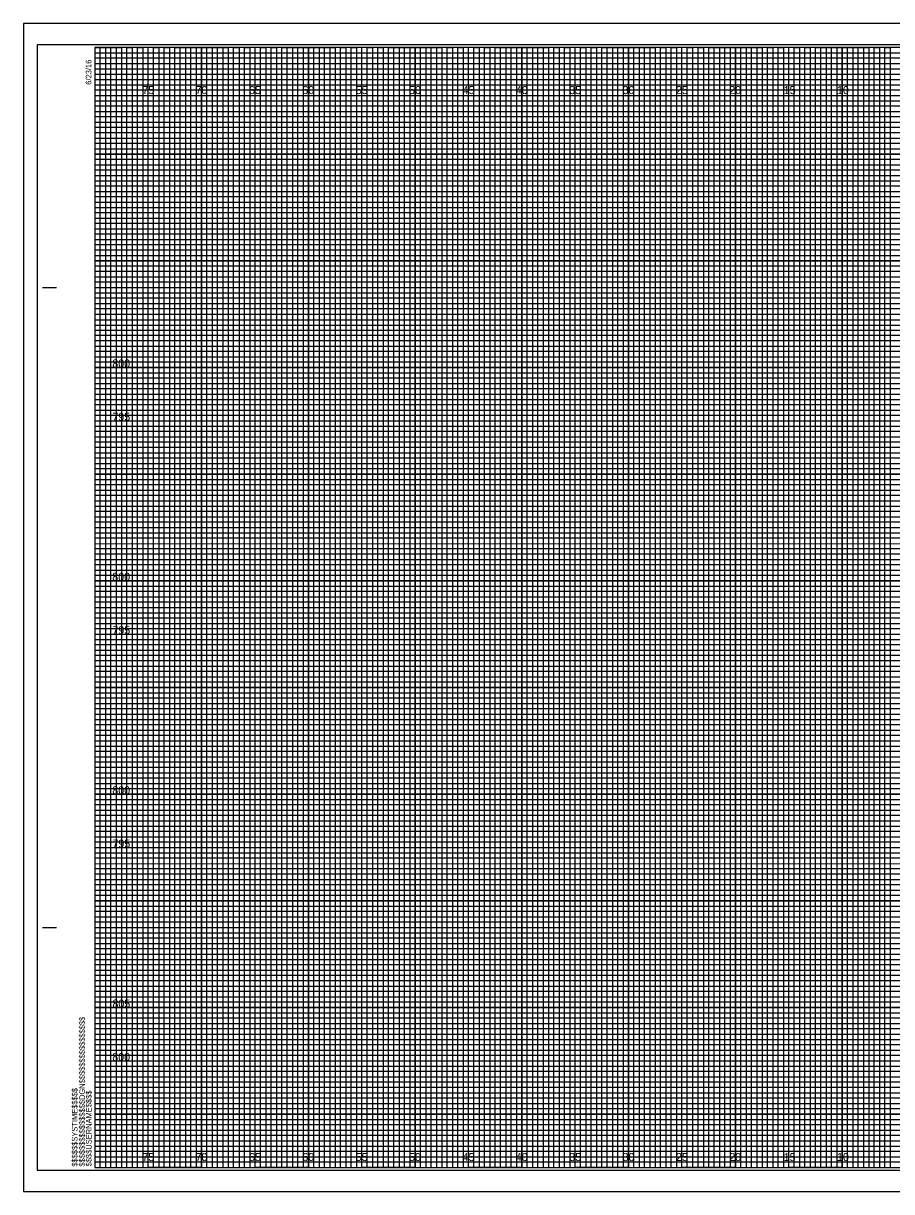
# Model space of a CAD drawing. Extents: x -7 to 162, y -2 to 107.
# Drawn here: x -6.7 to 74.6, y -2.3 to 107.3 of the extents above; entities that cross this region are included whole.
import ezdxf

# ---------------------------------------------------------------- set-up
doc = ezdxf.new("R2010")
doc.units = 0
for name, color, linetype in [('Exist Cross Section Cell', 7, 'Continuous'), ('Exist XS Center Line Elevation Label', 7, 'Continuous'), ('Prop CMT Pvmt Course 2 Wedge', 7, 'Continuous'), ('Prop XS Elevation Labels', 7, 'Continuous'), ('Prop XS Hydro Elevations', 7, 'Continuous'), ('Prop XS SE Text', 7, 'Continuous'), ('Prop XS Side Slope Text', 7, 'Continuous'), ('Sheet Cutting Line CELL', 7, 'Continuous'), ('Sheet DOT Grid CELL', 7, 'Continuous'), ('Sheet Plot Border Inside CELL', 7, 'Continuous'), ('Sheet Plot Border Outside CELL', 7, 'Continuous')]:
    doc.layers.add(name, color=color, linetype=linetype)

msp = doc.modelspace()

# ---------------------------------------------------------------- linework, layer by layer
at = {"layer": 'Exist Cross Section Cell'}
for p, q in [((5, 105), (0, 105)), ((5, 0), (5, 105)), ((15, 105), (10, 105)), ((10, 105), (10, 0)), ((15, 0), (15, 105)), ((25, 105), (20, 105)), ((20, 105), (20, 0)), ((25, 0), (25, 105)), ((35, 105), (30, 105)), ((30, 105), (30, 0)), ((35, 0), (35, 105)), ((45, 105), (40, 105)), ((40, 105), (40, 0)), ((45, 0), (45, 105)), ((55, 105), (50, 105)), ((50, 105), (50, 0)), ((55, 0), (55, 105)), ((65, 105), (60, 105)), ((60, 105), (60, 0)), ((65, 0), (65, 105)), ((75, 105), (70, 105)), ((70, 105), (70, 0)), ((10, 0), (5, 0)), ((20, 0), (15, 0)), ((30, 0), (25, 0)), ((40, 0), (35, 0)), ((50, 0), (45, 0)), ((60, 0), (55, 0)), ((70, 0), (65, 0))]:
    msp.add_line(p, q, dxfattribs=at)
for points in [[(0, 100), (160, 100), (160, 95), (0, 95)], [(0, 90), (160, 90), (160, 85), (0, 85)], [(0, 80), (160, 80), (160, 75), (0, 75)], [(0, 70), (160, 70), (160, 65), (0, 65)], [(0, 60), (160, 60), (160, 55), (0, 55)], [(0, 50), (160, 50), (160, 45), (0, 45)], [(0, 40), (160, 40), (160, 35), (0, 35)], [(0, 30), (160, 30), (160, 25), (0, 25)], [(0, 20), (160, 20), (160, 15), (0, 15)], [(0, 10), (160, 10), (160, 5), (0, 5)]]:
    msp.add_lwpolyline(points, dxfattribs=at)
at = {"layer": 'Exist XS Center Line Elevation Label'}
for points in [[(0, 105), (2.5, 105), (2.5, 0), (7.5, 0), (7.5, 105), (12.5, 105), (12.5, 0), (17.5, 0), (17.5, 105), (22.5, 105), (22.5, 0), (27.5, 0), (27.5, 105), (32.5, 105), (32.5, 0), (37.5, 0), (37.5, 105), (42.5, 105), (42.5, 0), (47.5, 0), (47.5, 105), (52.5, 105), (52.5, 0), (57.5, 0), (57.5, 105), (62.5, 105), (62.5, 0), (67.5, 0), (67.5, 105), (72.5, 105), (72.5, 0), (77.5, 0)], [(0, 102.5), (137.5, 102.5)], [(0, 92.5), (160, 92.5), (160, 97.5), (0, 97.5)], [(0, 82.5), (160, 82.5), (160, 87.5), (0, 87.5)], [(0, 72.5), (160, 72.5), (160, 77.5), (0, 77.5)], [(0, 62.5), (160, 62.5), (160, 67.5), (0, 67.5)], [(0, 52.5), (160, 52.5), (160, 57.5), (0, 57.5)], [(0, 42.5), (160, 42.5), (160, 47.5), (0, 47.5)], [(0, 32.5), (160, 32.5), (160, 37.5), (0, 37.5)], [(0, 22.5), (160, 22.5), (160, 27.5), (0, 27.5)], [(0, 12.5), (160, 12.5), (160, 17.5), (0, 17.5)], [(0, 2.5), (160, 2.5), (160, 7.5), (0, 7.5)]]:
    msp.add_lwpolyline(points, dxfattribs=at)
at = {"layer": 'Prop CMT Pvmt Course 2 Wedge'}
for points in [[(0, 0), (0.5, 0), (0.5, 105), (1, 105), (1, 0)], [(1, 0), (1.5, 0), (1.5, 105), (2, 105), (2, 0)], [(2.5, 0), (3, 0), (3, 105), (3.5, 105), (3.5, 0)], [(3.5, 0), (4, 0), (4, 105), (4.5, 105), (4.5, 0)], [(5, 0), (5.5, 0), (5.5, 105), (6, 105), (6, 0)], [(6, 0), (6.5, 0), (6.5, 105), (7, 105), (7, 0)], [(7.5, 0), (8, 0), (8, 105), (8.5, 105), (8.5, 0)], [(8.5, 0), (9, 0), (9, 105), (9.5, 105), (9.5, 0)], [(10, 0), (10.5, 0), (10.5, 105), (11, 105), (11, 0)], [(11, 0), (11.5, 0), (11.5, 105), (12, 105), (12, 0)], [(12.5, 0), (13, 0), (13, 105), (13.5, 105), (13.5, 0)], [(13.5, 0), (14, 0), (14, 105), (14.5, 105), (14.5, 0)], [(15, 0), (15.5, 0), (15.5, 105), (16, 105), (16, 0)], [(16, 0), (16.5, 0), (16.5, 105), (17, 105), (17, 0)], [(17.5, 0), (18, 0), (18, 105), (18.5, 105), (18.5, 0)], [(18.5, 0), (19, 0), (19, 105), (19.5, 105), (19.5, 0)], [(20, 0), (20.5, 0), (20.5, 105), (21, 105), (21, 0)], [(21, 0), (21.5, 0), (21.5, 105), (22, 105), (22, 0)], [(22.5, 0), (23, 0), (23, 105), (23.5, 105), (23.5, 0)], [(23.5, 0), (24, 0), (24, 105), (24.5, 105), (24.5, 0)], [(25, 0), (25.5, 0), (25.5, 105), (26, 105), (26, 0)], [(26, 0), (26.5, 0), (26.5, 105), (27, 105), (27, 0)], [(27.5, 0), (28, 0), (28, 105), (28.5, 105), (28.5, 0)], [(28.5, 0), (29, 0), (29, 105), (29.5, 105), (29.5, 0)], [(30, 0), (30.5, 0), (30.5, 105), (31, 105), (31, 0)], [(31, 0), (31.5, 0), (31.5, 105), (32, 105), (32, 0)], [(32.5, 0), (33, 0), (33, 105), (33.5, 105), (33.5, 0)], [(33.5, 0), (34, 0), (34, 105), (34.5, 105), (34.5, 0)], [(35, 0), (35.5, 0), (35.5, 105), (36, 105), (36, 0)], [(36, 0), (36.5, 0), (36.5, 105), (37, 105), (37, 0)], [(37.5, 0), (38, 0), (38, 105), (38.5, 105), (38.5, 0)], [(38.5, 0), (39, 0), (39, 105), (39.5, 105), (39.5, 0)], [(40, 0), (40.5, 0), (40.5, 105), (41, 105), (41, 0)], [(41, 0), (41.5, 0), (41.5, 105), (42, 105), (42, 0)], [(42.5, 0), (43, 0), (43, 105), (43.5, 105), (43.5, 0)], [(43.5, 0), (44, 0), (44, 105), (44.5, 105), (44.5, 0)], [(45, 0), (45.5, 0), (45.5, 105), (46, 105), (46, 0)], [(46, 0), (46.5, 0), (46.5, 105), (47, 105), (47, 0)], [(47.5, 0), (48, 0), (48, 105), (48.5, 105), (48.5, 0)], [(48.5, 0), (49, 0), (49, 105), (49.5, 105), (49.5, 0)], [(50, 0), (50.5, 0), (50.5, 105), (51, 105), (51, 0)], [(51, 0), (51.5, 0), (51.5, 105), (52, 105), (52, 0)], [(52.5, 0), (53, 0), (53, 105), (53.5, 105), (53.5, 0)], [(53.5, 0), (54, 0), (54, 105), (54.5, 105), (54.5, 0)], [(55, 0), (55.5, 0), (55.5, 105), (56, 105), (56, 0)], [(56, 0), (56.5, 0), (56.5, 105), (57, 105), (57, 0)], [(57.5, 0), (58, 0), (58, 105), (58.5, 105), (58.5, 0)], [(58.5, 0), (59, 0), (59, 105), (59.5, 105), (59.5, 0)], [(60, 0), (60.5, 0), (60.5, 105), (61, 105), (61, 0)], [(61, 0), (61.5, 0), (61.5, 105), (62, 105), (62, 0)], [(62.5, 0), (63, 0), (63, 105), (63.5, 105), (63.5, 0)], [(63.5, 0), (64, 0), (64, 105), (64.5, 105), (64.5, 0)], [(65, 0), (65.5, 0), (65.5, 105), (66, 105), (66, 0)], [(66, 0), (66.5, 0), (66.5, 105), (67, 105), (67, 0)], [(67.5, 0), (68, 0), (68, 105), (68.5, 105), (68.5, 0)], [(68.5, 0), (69, 0), (69, 105), (69.5, 105), (69.5, 0)], [(70, 0), (70.5, 0), (70.5, 105), (71, 105), (71, 0)], [(71, 0), (71.5, 0), (71.5, 105), (72, 105), (72, 0)], [(72.5, 0), (73, 0), (73, 105), (73.5, 105), (73.5, 0)], [(73.5, 0), (74, 0), (74, 105), (74.5, 105), (74.5, 0)]]:
    msp.add_lwpolyline(points, dxfattribs=at)
at = {"layer": 'Prop XS Hydro Elevations'}
for p, q in [((-4.9, 82.5), (-3.65, 82.5)), ((-4.85, 82.5), (-3.6, 82.5)), ((-4.9, 22.5), (-3.65, 22.5)), ((-4.85, 22.5), (-3.6, 22.5)), ((0, 0), (0, 0)), ((0, 0), (0, 0)), ((0, 0), (0, 0)), ((0, 0), (0, 0)), ((0, 0), (0, 0)), ((0, 0), (0, 0)), ((0, 0), (0, 0))]:
    msp.add_line(p, q, dxfattribs=at)
msp.add_lwpolyline([(160, 105), (0, 105), (0, 0), (160, 0)], close=True, dxfattribs=at)
at = {"layer": 'Prop XS Side Slope Text'}
for p, q in [((0, 104.5), (130, 104.5)), ((130, 103.99), (0, 103.99)), ((0, 103.99), (0, 103.5)), ((0, 103.5), (130, 103.5)), ((130, 102.95), (0, 102.95)), ((0, 102.95), (0, 102)), ((0, 102), (160, 102))]:
    msp.add_line(p, q, dxfattribs=at)
for points in [[(0, 101.5), (135, 101.5), (160, 101.5), (160, 101), (0, 101)], [(0, 100.5), (160, 100.5), (160, 99.5), (0, 99.5)], [(0, 99), (160, 99), (160, 98.5), (0, 98.49)], [(0, 98), (160, 98), (160, 97), (0, 97)], [(0, 96.5), (160, 96.5), (160, 96), (0, 96)], [(0, 95.5), (160, 95.5), (160, 94.5), (0, 94.5)], [(0, 94), (160, 94), (160, 93.5), (0, 93.5)], [(0, 93), (160, 93), (160, 92), (0, 92)], [(0, 91.5), (160, 91.5), (160, 91), (0, 91)], [(0, 90.5), (160, 90.5), (160, 89.5), (0, 89.5)], [(0, 89), (160, 89), (160, 88.5), (0, 88.5)], [(0, 88), (160, 88), (160, 86.98), (160, 86.5), (160, 86), (0, 86)], [(0, 87), (160, 87), (160, 86.5), (0, 86.5)], [(0, 85.5), (160, 85.5), (160, 84.5), (0, 84.52)], [(0, 84.52), (160, 84.5), (160, 84), (0, 84)], [(0, 83.5), (160, 83.5), (160, 83), (0, 83)], [(0, 82), (160, 82), (160, 81.5), (0, 81.5)], [(0, 81), (160, 81), (160, 80.5), (0, 80.5)], [(-0.04, 79.45), (160, 79.45), (160, 78.94), (-0.04, 78.94)], [(0, 78.5), (160, 78.5), (160, 78), (0, 78)], [(0, 77), (160, 77), (160, 76.5), (0, 76.5)], [(0, 76), (160, 76), (160, 75.5), (0, 75.5)], [(0, 74.5), (160, 74.5), (160, 74), (0, 74)], [(0, 73.5), (160, 73.5), (160, 73), (0, 73)], [(0, 72), (160, 72), (160, 71.5), (0, 71.5)], [(0, 71), (160, 71), (160, 70.5), (0, 70.5)], [(0, 69.5), (160, 69.5), (160, 68.99), (0, 69)], [(0, 68.5), (160, 68.5), (160, 68), (0, 68)], [(0, 67), (160, 67), (160, 66.5), (0, 66.5)], [(0, 66), (160, 66), (160, 65.5), (0, 65.5)], [(0, 64.5), (160, 64.5), (160, 64), (0, 64)], [(0, 63.5), (160, 63.5), (160, 63), (0, 63)], [(0, 62), (160, 62), (160, 61.5), (0, 61.5)], [(0, 61), (160, 61), (160, 60.5), (0, 60.5)], [(0, 59.5), (160, 59.5), (160, 59), (0, 59)], [(0, 58.5), (160.03, 58.45), (160, 58), (0, 58)], [(0, 57), (160, 57), (160, 56.5), (0, 56.5)], [(0, 56), (160, 56), (160, 55.5), (0, 55.5)], [(0, 54.5), (160, 54.5), (160, 54), (0, 54)], [(0, 53.5), (160, 53.5), (160, 53), (0, 53)], [(0, 52), (160, 52), (160, 51.5), (0, 51.5)], [(0, 51), (160, 51), (160, 50.5), (0, 50.5)], [(0, 49.5), (160, 49.5), (160, 49), (0, 49)], [(0, 48.5), (160, 48.5), (160, 48), (0, 48)], [(0, 47), (160, 47), (160, 46.5), (0, 46.5)], [(0, 46), (160, 46), (160, 45.5), (0, 45.5)], [(0, 44.5), (160, 44.5), (160, 44), (0, 44)], [(0, 43.5), (160, 43.5), (160, 43), (0, 43)], [(0, 42), (160, 42), (160, 41.5), (0, 41.5)], [(0, 41), (160, 41), (160, 40.5), (0, 40.5)], [(0, 39.5), (160, 39.5), (160, 38.99), (0, 39)], [(0, 38.5), (160, 38.5), (160, 38), (0, 38)], [(0, 37), (160, 37), (160, 36.5), (0, 36.5)], [(0, 36), (160, 36), (160, 35.5), (0, 35.5)], [(0, 34.5), (160, 34.5), (160, 34), (0, 34)], [(0, 33.5), (160, 33.5), (160, 33), (0, 33)], [(0, 32), (160, 32), (160, 31.5), (0, 31.5)], [(0, 31), (160, 31), (160, 30.5), (0, 30.5)], [(0, 29.5), (160, 29.5), (160, 29), (0, 29)], [(0, 28.5), (160.03, 28.46), (160, 28), (0, 28)], [(0, 27), (160, 27), (160, 26.5), (0, 26.5)], [(0, 26), (160, 26), (160, 25.5), (0, 25.5)], [(0, 24.5), (160, 24.5), (160, 24), (0, 24)], [(0, 23.5), (160, 23.5), (160, 23), (0, 23)], [(0, 22), (160, 22), (160, 21.5), (0, 21.5)], [(0, 21), (160, 21), (160, 20.5), (0, 20.5)], [(0, 19.5), (160, 19.5), (160, 19), (0, 19)], [(0, 18.5), (160, 18.5), (160, 18), (0, 18)], [(0, 17), (160, 17), (160, 16.5), (0, 16.5)], [(0, 16), (160, 16), (160, 15.5), (0, 15.5)], [(0, 14.5), (160, 14.5), (160, 14), (0, 14)], [(0, 13.5), (160, 13.5), (160, 13), (0, 13)], [(0, 12), (160, 12), (160, 11.5), (0, 11.5)], [(0, 11), (160, 11), (160, 10.5), (0, 10.5)], [(0, 9.5), (160, 9.5), (160, 9), (0, 9)], [(0, 8.5), (160, 8.5), (160, 8), (0, 8)], [(0, 7), (160, 7), (160, 6.5), (0, 6.5)], [(0, 6), (160, 6), (160, 5.5), (0, 5.5)], [(0, 4.5), (160, 4.5), (160, 4), (0, 4)], [(0, 3.5), (160, 3.5), (160, 3), (0, 3)], [(0, 2), (160, 2), (160, 1.5), (0, 1.5)], [(0, 1), (160, 1), (160, 0.5), (0, 0.5)]]:
    msp.add_lwpolyline(points, dxfattribs=at)
at = {"layer": 'Sheet Cutting Line CELL'}
for p, q in [((161.65, 107.25), (-6.7, 107.25)), ((-6.7, 107.25), (-6.7, -2.25)), ((-6.7, -2.25), (161.65, -2.25))]:
    msp.add_line(p, q, dxfattribs=at)
at = {"layer": 'Sheet DOT Grid CELL'}
for p, q in [((5, 0), (5, 105)), ((10, 0), (10, 105)), ((15, 0), (15, 105)), ((20, 0), (20, 105)), ((25, 0), (25, 105)), ((30, 0), (30, 105)), ((35, 0), (35, 105)), ((40, 0), (40, 105)), ((45, 0), (45, 105)), ((50, 0), (50, 105)), ((55, 0), (55, 105)), ((60, 0), (60, 105)), ((65, 0), (65, 105)), ((70, 0), (70, 105)), ((0, 100), (160, 100)), ((0, 95), (160, 95)), ((0, 90), (160, 90)), ((0, 85), (160, 85)), ((0, 80), (160, 80)), ((0, 75), (160, 75)), ((0, 70), (160, 70)), ((0, 65), (160, 65)), ((0, 60), (160, 60)), ((0, 55), (160, 55)), ((0, 50), (160, 50)), ((0, 45), (160, 45)), ((0, 40), (160, 40)), ((0, 35), (160, 35)), ((0, 30), (160, 30)), ((0, 25), (160, 25)), ((0, 20), (160, 20)), ((0, 15), (160, 15)), ((0, 10), (160, 10)), ((0, 5), (160, 5))]:
    msp.add_line(p, q, dxfattribs=at)
at = {"layer": 'Sheet Plot Border Inside CELL'}
msp.add_lwpolyline([(-5.4, -0.25), (161.2, -0.25), (161.2, 105.25), (-5.4, 105.25)], close=True, dxfattribs=at)
at = {"layer": 'Sheet Plot Border Outside CELL'}
msp.add_lwpolyline([(-6.7, -2.25), (161.65, -2.25), (161.65, 107.25), (-6.7, 107.25)], close=True, dxfattribs=at)

# ---------------------------------------------------------------- texts
at = {"layer": 'Prop XS Elevation Labels'}
for s, p in [('800', (1.63, 75)), ('795', (1.64, 70)), ('800', (1.63, 55)), ('795', (1.64, 50)), ('800', (1.63, 35)), ('795', (1.64, 30)), ('805', (1.64, 15)), ('800', (1.63, 10))]:
    msp.add_text(s, height=0.75, dxfattribs=at).set_placement(p)
at = {"layer": 'Prop XS Hydro Elevations'}
for s, p in [('6/23/16', (-0.33, 101.5)), ('$$$$$$$$$$$$$$$$DGN$$$$$$$$$$$$$$$$', (-0.94, 0.09)), ('$$$$$$SYSTIME$$$$$', (-1.63, 0.09)), ('$$$$USERNAME$$$$', (-0.31, 0.12))]:
    msp.add_text(s, height=0.525, rotation=90, dxfattribs=at).set_placement(p)
at = {"layer": 'Prop XS SE Text'}
for s, p in [('75', (4.44, 100.62)), ('70', (9.43, 100.62)), ('65', (14.44, 100.62)), ('60', (19.43, 100.62)), ('55', (24.44, 100.62)), ('50', (29.43, 100.62)), ('45', (34.44, 100.62)), ('40', (39.43, 100.62)), ('35', (44.44, 100.62)), ('30', (49.43, 100.62)), ('25', (54.44, 100.62)), ('20', (59.43, 100.62)), ('15', (64.53, 100.62)), ('10', (69.52, 100.62)), ('75', (4.44, 0.62)), ('70', (9.43, 0.62)), ('65', (14.44, 0.62)), ('60', (19.43, 0.62)), ('55', (24.44, 0.62)), ('50', (29.43, 0.62)), ('45', (34.44, 0.62)), ('40', (39.43, 0.62)), ('35', (44.44, 0.62)), ('30', (49.43, 0.62)), ('25', (54.44, 0.62)), ('20', (59.43, 0.62)), ('15', (64.53, 0.62)), ('10', (69.52, 0.62))]:
    msp.add_text(s, height=0.75, dxfattribs=at).set_placement(p)

doc.saveas('drawing.dxf')
